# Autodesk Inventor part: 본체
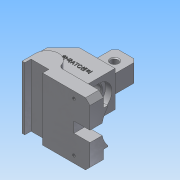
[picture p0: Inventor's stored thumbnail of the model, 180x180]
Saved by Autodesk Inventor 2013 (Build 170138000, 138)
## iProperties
Created: 2016-11
Part Number: 본체
Material: 알루미늄 6061
Document SubType Name: Modeling
Designer: Administrator
Density: 2.71 g/cm^3
Mass: 462.906 g
Surface Area: 317.29 cm^2
Volume: 170.814 cm^3
Author: Administrator
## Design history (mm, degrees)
sketch "스케치1"
  geometry: L1 (-27, 0)-(-27, -30); L2 (-27, -30)-(31, -30); L3 (31, -30)-(31, 18); L4 (31, 18)-(-9, 18); L5 (-9, 18)-(-27, 0); 1 further point
  constraints: 10 end point, 1 horizontal, 1 parallel, 1 perpendicular, 1 vertical
  dimensions: "d3" = 30 distance from line of point (0, 0) L2; "d4" = 27 distance from line of point (0, 0) L1; "d7" = 45 deg angle of L5 L4; "d8" = 58 distance between parallel lines of L3 L1; "d9" = 18 distance from line of L4.end L1; "d10" = 48 distance between parallel lines of L2 L4
extrude "돌출1" new body sketch "스케치1" stored distance "d11" = 40; taper "d12" = 0 deg
sketch "스케치3"
  geometry: C1 r 14.5 at (20, 30); 1 further point
  constraints: 1 centre point, 1 coincident
  dimensions: "d13" = 29 diameter of C1
extrude "돌출2" cut sketch "스케치3" distance "d14" = 7; taper "d15" = 0 deg
sketch "스케치4"
  geometry: C1 r 14.5 at (0, 0) reference; C2 r 10 at (0, 0)
  constraints: 1 centre point, 1 coincident
  dimensions: "d16" = 20 diameter of C2
extrude "돌출3" cut sketch "스케치4" stored distance "d17" = 7; taper "d18" = 0 deg
sketch "스케치6"
  geometry: L1 (31, 14.5)-(24, 14.5) reference; L2 (24, 14.5)-(24, 10) reference; L3 (24, 10)-(-17, 10) reference; L4 (-17, 10)-(-9, 18) reference; L5 (-9, 18)-(31, 18) reference; L6 (31, 18)-(31, 14.5) reference; L7 (24, -14.5)-(31, -14.5) reference; L8 (31, -14.5)-(31, -30) reference; L9 (31, -30)-(-27, -30) reference; L10 (-27, -30)-(-27, -10) reference; L11 (-27, -10)-(24, -10) reference; L12 (24, -10)-(24, -14.5) reference; L13 (17.292, -27)-(63, -27); L14 (-13, -27)-(-13, -42); L15 (-13, -42)-(-10, -42); L16 (-10, -42)-(-10, -35); L17 (-10, -35)-(10, -35); L18 (10, -35)-(10, -42); L19 (10, -42)-(63, -42); L20 (63, -42)-(63, -27); A1 r 13 centre (0, -27) between (12.488, -23.389) and (-13, -27); A2 r 5 centre (17.292, -22) between (12.488, -23.389) and (17.292, -27); 1 further point
  constraints: 16 end point, 4 point on circle, 3 parallel, 3 perpendicular, 3 tangent, 2 centre point, 2 collinear, 1 vertical
  dimensions: "d21" = 90 distance between parallel lines of L20 L10; "d22" = 7 distance between parallel lines of L15 L17; "d23" = 3 distance between parallel lines of L16 L14; "d24" = 20 distance between parallel lines of L18 L16; "d25" = 63 distance from line of L20 A1.centre; "d26" = 15 distance between parallel lines of L19 L13; "d27" = 60 distance between parallel lines of L15 L5; "d28" = 5 radius of A2; "d29" = 13 radius of A1; "d30" = 15 distance from line of L19 A1.centre
extrude "돌출4" join sketch "스케치6" stored distance "d31" = 70; taper "d32" = 0 deg
sketch "스케치7"
  geometry: L1 (24, 10)-(-17, 10) reference; L2 (-17, 10)-(-9, 18) reference; L3 (-9, 18)-(31, 18) reference; L4 (31, 18)-(31, 14.5) reference; L5 (31, 14.5)-(24, 14.5) reference; L6 (24, 14.5)-(24, 10) reference; L7 (-27, -10)-(24, -10) reference; L8 (24, -10)-(24, -14.5) reference; L9 (24, -14.5)-(31, -14.5) reference; L10 (31, -14.5)-(31, -27) reference; L11 (31, -27)-(63, -27) reference; L12 (63, -27)-(63, -42) reference; L13 (63, -42)-(10, -42) reference; L14 (10, -42)-(10, -35) reference; L15 (10, -35)-(-10, -35) reference; L16 (-10, -35)-(-10, -42) reference; L17 (-10, -42)-(-13, -42) reference; L18 (-13, -42)-(-13, -30) reference; L19 (-13, -30)-(-27, -30) reference; L20 (-27, -30)-(-27, -10) reference; L21 (26, 18)-(1, 18); L22 (1, 18)-(1, 48); L23 (1, 48)-(26, 48); L24 (26, 48)-(26, 18); 2 further points
  constraints: 8 end point, 2 parallel, 1 horizontal, 1 midpoint, 1 perpendicular, 1 point on line
  dimensions: "d33" = 90 distance between parallel lines of L23 L13; "d34" = 25 distance of L22.end L23.end; "d35" = 5 distance between parallel lines of L24 L4
extrude "돌출5" join sketch "스케치7" stored distance "d36" = 20; taper "d37" = 0 deg
sketch "스케치9"
  geometry: L1 (24, 10)-(-17, 10) reference; L2 (-17, 10)-(-9, 18) reference; L3 (-9, 18)-(1, 18) reference; L4 (1, 18)-(1, 48) reference; L5 (1, 48)-(26, 48) reference; L6 (26, 48)-(26, 18) reference; L7 (26, 18)-(31, 18) reference; L8 (31, 18)-(31, 14.5) reference; L9 (31, 14.5)-(24, 14.5) reference; L10 (24, 14.5)-(24, 10) reference; L11 (-27, -10)-(24, -10) reference; L12 (24, -10)-(24, -14.5) reference; L13 (24, -14.5)-(31, -14.5) reference; L14 (31, -14.5)-(31, -27) reference; L15 (31, -27)-(63, -27) reference; L16 (63, -27)-(63, -42) reference; L17 (63, -42)-(10, -42) reference; L18 (10, -42)-(10, -35) reference; L19 (10, -35)-(-10, -35) reference; L20 (-10, -35)-(-10, -42) reference; L21 (-10, -42)-(-13, -42) reference; L22 (-13, -42)-(-13, -30) reference; L23 (-13, -30)-(-27, -30) reference; L24 (-27, -30)-(-27, -10) reference; C1 r 4 at (13.5, 35); 1 further point
  constraints: 1 centre point
  dimensions: "d40" = 8 diameter of C1; "d41" = 35 vertical distance of point (0, 0) C1.centre; "d42" = 12.5 distance from line of C1.centre L4
extrude "돌출6" cut sketch "스케치9" stored distance "d43" = 20; taper "d44" = 0 deg
sketch "스케치13"
  geometry: L1 (24, 10)-(-17, 10) reference; L2 (-17, 10)-(-9, 18) reference; L3 (-9, 18)-(1, 18) reference; L4 (1, 18)-(1, 48) reference; L5 (1, 48)-(26, 48) reference; L6 (26, 48)-(26, 18) reference; L7 (26, 18)-(31, 18) reference; L8 (31, 18)-(31, 14.5) reference; L9 (31, 14.5)-(24, 14.5) reference; L10 (24, 14.5)-(24, 10) reference; L11 (-27, -10)-(24, -10) reference; L12 (24, -10)-(24, -14.5) reference; L13 (24, -14.5)-(31, -14.5) reference; L14 (31, -14.5)-(31, -27) reference; L15 (31, -27)-(63, -27) reference; L16 (63, -27)-(63, -42) reference; L17 (63, -42)-(10, -42) reference; L18 (10, -42)-(10, -35) reference; L19 (10, -35)-(-10, -35) reference; L20 (-10, -35)-(-10, -42) reference; L21 (-10, -42)-(-13, -42) reference; L22 (-13, -42)-(-13, -30) reference; L23 (-13, -30)-(-27, -30) reference; L24 (-27, -30)-(-27, -10) reference; L25 (31, -27)-(63, -27); L26 (63, -27)-(63, -22); L27 (63, -22)-(31, -22); L28 (31, -22)-(31, -27); C1 r 4 at (13.5, 35) reference; 1 further point
  constraints: 8 end point, 2 parallel, 1 horizontal, 1 perpendicular
  dimensions: "d45" = 90 distance between parallel lines of L26 L24; "d46" = 20 distance between parallel lines of L17 L27
extrude "돌출7" join sketch "스케치13" stored distance "d47" = 40; taper "d48" = 0 deg
sketch "스케치17"
  geometry: L1 (70, 0)-(0, 0) reference; L2 (55, 20)-(15, 20) reference; L3 (41, 13.627)-(41, 0); L4 (41, 0)-(29, 0); L5 (29, 0)-(29, 13.627); A1 r 29 centre (35, 42) between (41, 13.627) and (53.894, 20); A2 r 29 centre (35, 42) between (16.106, 20) and (29, 13.627); 2 further points
  constraints: 6 end point, 4 point on circle, 2 centre point, 2 midpoint, 2 parallel, 2 point on line, 1 coincident, 1 vertical alignment
  dimensions: "d63" = 12 distance between parallel lines of L3 L5; "d65" = 29 radius of A2; "d66" = 29 radius of A1; "d67" = 13.62748 distance of L4.end L5.end
extrude "돌출9" cut sketch "스케치17" distance "d68" = 18; taper "d69" = 0 deg
sketch "스케치18"
  geometry: L1 (45.708, -15)-(0, -15) reference; L2 (45.708, -15)-(45.708, 0) reference; 2 further points
  dimensions: "d70" = 18 distance from line of point (27.708, -7.5) L2; "d71" = 7.5 distance from line of point (27.708, -7.5) L1
hole "구멍1" sketch "스케치18" at (27.708, -7.5) diameter "d72" = 3.242; stored, may be unused: countersink angle "d76" = 90 deg, drill point angle "d78" = 0 deg; dims "d73" = 6, "d74" = 4, "d75" = 2, "d77" = 8
chamfer "모따기1" distance "d79" = 4; stored, may be unused: second distance "d80" = 2, angle "d81" = 45 deg
chamfer "모따기2" distance "d82" = 1; stored, may be unused: second distance "d83" = 2, angle "d84" = 45 deg
chamfer "모따기3" distance "d85" = 4; stored, may be unused: second distance "d86" = 2, angle "d87" = 45 deg
fillet "모깎기1" dims "d88" = 3
chamfer "모따기4" distance "d89" = 5; stored, may be unused: second distance "d90" = 2, angle "d91" = 45 deg
sketch "스케치19"
  geometry: L1 (31, -19)-(31, 18) reference; L2 (31, 18)-(-9, 18) reference; 2 further points
  constraints: 1 other
  dimensions: "d92" = 25 distance from line of point (6, 0) L1; "d93" = 18 distance from line of point (6, 0) L2
feature "엠보싱1" sketch "스케치19" dims "d4" = 27, "d94" = 0.5, "d95" = 0
node "솔리드1"
mirror "대칭1"
node "절단 모서리 투영2"
node "절단 모서리 투영3"
node "절단 모서리 투영4"
node "절단 모서리 투영5"
other parameters: "d49" = 58, "d62" = 58
